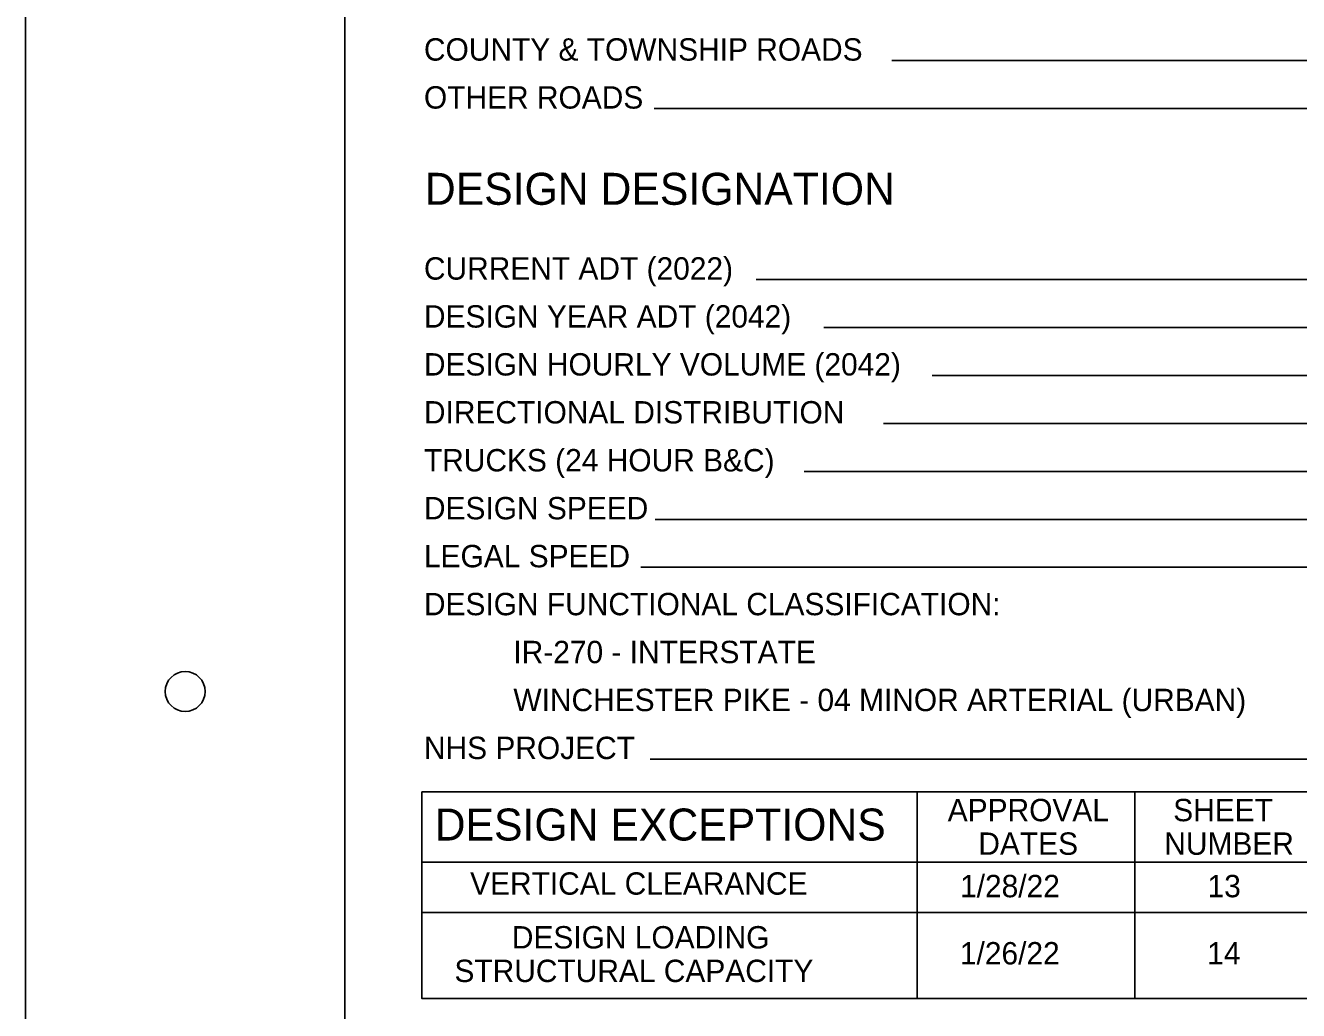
# Model space of a CAD drawing. Extents: x 0 to 34, y 0 to 22.
# Drawn here: x 0 to 7.97, y 4.75 to 10.92 of the extents above; entities that cross this region are included whole.
import ezdxf

# ---------------------------------------------------------------- set-up
doc = ezdxf.new("R2010")
doc.units = 0
for name, color, linetype in [('SH_Border', 7, 'Continuous'), ('SH_Cut_Line', 7, 'Continuous'), ('SH_Data', 7, 'Continuous')]:
    doc.layers.add(name, color=color, linetype=linetype)

msp = doc.modelspace()

# ---------------------------------------------------------------- linework, layer by layer
at = {"layer": 'SH_Border'}
msp.add_lwpolyline([(2, 21.5), (33.5, 21.5), (33.5, 0.5), (2, 0.5)], close=True, dxfattribs=at)
msp.add_circle((1, 6.75), 0.125, dxfattribs=at)
at = {"layer": 'SH_Cut_Line'}
msp.add_lwpolyline([(0, 0), (34, 0), (34, 22), (0, 22)], close=True, dxfattribs=at)
at = {"layer": 'SH_Data'}
for p, q in [((8.2, 10.6975), (5.424, 10.6975)), ((8.2, 10.3975), (3.9348, 10.3975)), ((8.1424, 9.3271), (4.5737, 9.3271)), ((8.1368, 9.0271), (4.9987, 9.0271)), ((8.1368, 8.7271), (5.6758, 8.7271)), ((8.1368, 8.4271), (5.3711, 8.4271)), ((8.1368, 8.1271), (4.8746, 8.1271)), ((8.1368, 7.8271), (3.9417, 7.8271)), ((8.1368, 7.5271), (3.8514, 7.5271)), ((8.1368, 6.3271), (3.9116, 6.3271)), ((5.5829, 6.1213), (5.5829, 4.8286)), ((6.9451, 6.1213), (6.9451, 4.8286)), ((2.4814, 5.6817), (8.0329, 5.6817)), ((2.4814, 5.3677), (8.0329, 5.3677))]:
    msp.add_line(p, q, dxfattribs=at)
msp.add_lwpolyline([(2.4814, 6.1213), (8.0329, 6.1213), (8.0329, 4.8286), (2.4814, 4.8286)], close=True, dxfattribs=at)

# ---------------------------------------------------------------- texts
for s, height, p in [('COUNTY & TOWNSHIP ROADS', 0.14, (2.4944, 10.6975)), ('OTHER ROADS', 0.14, (2.4944, 10.3975)), ('DESIGN DESIGNATION', 0.2, (2.5, 9.7955)), ('CURRENT ADT (2022)', 0.14, (2.4944, 9.3271)), ('DESIGN YEAR ADT (2042)', 0.14, (2.4944, 9.0271)), ('DESIGN HOURLY VOLUME (2042)', 0.14, (2.4944, 8.7271)), ('DIRECTIONAL DISTRIBUTION', 0.14, (2.4944, 8.4271)), ('TRUCKS (24 HOUR B&C)', 0.14, (2.4944, 8.1271)), ('DESIGN SPEED', 0.14, (2.4944, 7.8271)), ('LEGAL SPEED', 0.14, (2.4944, 7.5271)), ('DESIGN FUNCTIONAL CLASSIFICATION:', 0.14, (2.4944, 7.2271)), ('IR-270 - INTERSTATE', 0.14, (3.0544, 6.9271)), ('WINCHESTER PIKE - 04 MINOR ARTERIAL (URBAN)', 0.14, (3.0544, 6.6271)), ('NHS PROJECT', 0.14, (2.4944, 6.3271)), ('APPROVAL', 0.14, (5.7732, 5.9381)), ('SHEET', 0.14, (7.1846, 5.9381)), ('DESIGN EXCEPTIONS', 0.2, (2.5617, 5.8175)), ('DATES', 0.14, (5.965, 5.7281)), ('NUMBER', 0.14, (7.1289, 5.7281)), ('VERTICAL CLEARANCE', 0.14, (2.7835, 5.4785)), ('1/28/22', 0.14, (5.8506, 5.4625)), ('13', 0.14, (7.3998, 5.4625)), ('DESIGN LOADING', 0.14, (3.0447, 5.1419)), ('1/26/22', 0.14, (5.8495, 5.042)), ('14', 0.14, (7.3976, 5.042)), ('STRUCTURAL CAPACITY', 0.14, (2.6854, 4.9319))]:
    msp.add_text(s, height=height, dxfattribs=at).set_placement(p)

doc.saveas('drawing.dxf')
